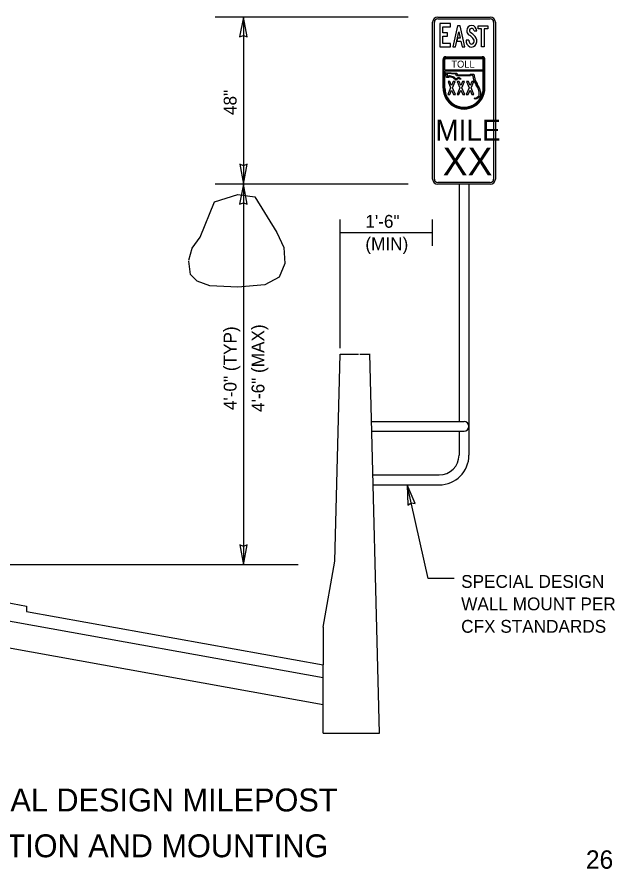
# Model space of a CAD drawing. Extents: x 57428 to 58066, y 11696 to 12105.
# Drawn here: x 57924.4 to 58054.8, y 11706.5 to 11892.4 of the extents above; entities that cross this region are included whole.
import ezdxf

# ---------------------------------------------------------------- set-up
doc = ezdxf.new("R2010")
doc.units = 0
for name, color, linetype in [('52', 7, 'Continuous'), ('62', 7, 'Continuous'), ('DimLines_dp', 7, 'Continuous'), ('NonPlottingEle_dp', 7, 'Continuous'), ('SheetLines_dp', 7, 'Continuous'), ('SignPanel', 7, 'Continuous'), ('TextMinor', 7, 'Continuous'), ('XSGrdLine_ex', 7, 'Continuous')]:
    doc.layers.add(name, color=color, linetype=linetype)

msp = doc.modelspace()

# ---------------------------------------------------------------- linework, layer by layer
at = {"layer": '52'}
msp.add_line((57985.74, 11772.84), (57842.57, 11772.84), dxfattribs=at)
at = {"layer": '62'}
msp.add_lwpolyline([(57961.87, 11839.32), (57962.57, 11841.92), (57964.37, 11844.33), (57967.47, 11852.08), (57972.57, 11853.68), (57976.27, 11853.18), (57981.07, 11845.33), (57982.58, 11842.12), (57982.78, 11838.62), (57981.57, 11835.62), (57978.47, 11833.91), (57972.57, 11833.41), (57966.47, 11833.71), (57963.67, 11834.71), (57962.27, 11836.22), (57961.87, 11839.12)], dxfattribs=at)
at = {"layer": 'DimLines_dp'}
for p, q in [((58009.68, 11892.38), (57967.6, 11892.38)), ((57973.78, 11892.38), (57972.94, 11888.03)), ((57973.78, 11892.38), (57973.78, 11855.89)), ((57974.59, 11888.03), (57973.78, 11892.38)), ((57972.94, 11888.03), (57973.78, 11888.36)), ((57973.78, 11888.36), (57974.59, 11888.03)), ((57973.78, 11861.88), (57973.78, 11772.84)), ((57973.78, 11859.91), (57972.97, 11860.24)), ((57972.97, 11860.24), (57973.78, 11855.89)), ((57973.78, 11859.91), (57972.97, 11860.24)), ((57972.97, 11860.24), (57973.78, 11855.89)), ((57973.78, 11855.89), (57974.62, 11860.24)), ((57974.62, 11860.24), (57973.78, 11859.91)), ((57973.78, 11855.89), (57974.62, 11860.24)), ((57974.62, 11860.24), (57973.78, 11859.91)), ((58009.68, 11855.89), (57967.6, 11855.89)), ((57973.78, 11855.89), (57972.94, 11851.54)), ((57974.59, 11851.54), (57973.78, 11855.89)), ((57972.94, 11851.54), (57973.78, 11851.87)), ((57973.78, 11851.87), (57974.59, 11851.54)), ((57994.89, 11820.11), (57994.89, 11848.22)), ((58015.03, 11842.47), (58015.03, 11848.22)), ((57994.89, 11845.38), (58015.03, 11845.38)), ((58009.47, 11790.29), (58009.6, 11785.87)), ((58011.21, 11786.23), (58009.47, 11790.29)), ((58014.05, 11769.85), (58009.47, 11790.29)), ((58009.6, 11785.87), (58010.35, 11786.37)), ((58010.35, 11786.37), (58011.21, 11786.23)), ((57973.78, 11776.86), (57972.97, 11777.19)), ((57972.97, 11777.19), (57973.78, 11772.84)), ((57973.78, 11772.84), (57974.62, 11777.19)), ((57974.62, 11777.19), (57973.78, 11776.86)), ((58019.7, 11769.85), (58014.05, 11769.85))]:
    msp.add_line(p, q, dxfattribs=at)
at = {"layer": 'NonPlottingEle_dp'}
for p, q in [((58020.8, 11855.89), (58020.8, 11804.14)), ((58022.96, 11855.89), (58022.96, 11796.77)), ((58001.72, 11804.14), (58021.88, 11804.14)), ((58001.78, 11801.98), (58021.88, 11801.98)), ((58020.8, 11801.98), (58020.8, 11796.77)), ((58002.02, 11792.45), (58016.48, 11792.45)), ((58002.08, 11790.29), (58016.48, 11790.29))]:
    msp.add_line(p, q, dxfattribs=at)
for centre, radius, end in [((58021.88, 11803.06), 1.08, 90), ((58016.48, 11796.77), 4.32, 0), ((58016.48, 11796.77), 6.48, 0)]:
    msp.add_arc(centre, radius, 270, end, dxfattribs=at)
at = {"layer": 'SignPanel'}
for p, q in [((58024.07, 11889.38), (58024.65, 11889.38)), ((58024.07, 11889.38), (58024.65, 11889.38)), ((58024.07, 11889.38), (58024.65, 11889.38)), ((58022.93, 11887.34), (58022.34, 11887.34)), ((58022.93, 11887.34), (58022.34, 11887.34)), ((58022.93, 11887.34), (58022.34, 11887.34)), ((58017.32, 11876.87), (58017.32, 11883.15)), ((58017.51, 11876.87), (58017.51, 11883.15)), ((58017.69, 11880.87), (58017.69, 11883.15)), ((58017.89, 11883.72), (58025.87, 11883.72)), ((58017.89, 11883.53), (58025.87, 11883.53)), ((58017.89, 11883.33), (58025.87, 11883.33)), ((58026.06, 11880.87), (58026.06, 11883.15)), ((58026.25, 11876.87), (58026.25, 11883.15)), ((58026.44, 11876.87), (58026.44, 11883.15)), ((58017.69, 11880.87), (58026.06, 11880.87)), ((58017.69, 11876.87), (58017.69, 11880.67)), ((58017.69, 11880.67), (58026.06, 11880.67)), ((58026.06, 11876.87), (58026.06, 11880.67)), ((58018.08, 11879.22), (58017.91, 11880.31)), ((58017.91, 11880.31), (58020.29, 11880.12)), ((58018.53, 11879.16), (58018.08, 11879.22)), ((58020.13, 11879.91), (58018.18, 11880.06)), ((58018.18, 11880.06), (58018.28, 11879.43)), ((58018.28, 11879.43), (58018.47, 11879.4)), ((58018.47, 11879.4), (58018.74, 11879.61)), ((58018.78, 11879.36), (58018.53, 11879.16)), ((58018.74, 11879.61), (58019.66, 11879.32)), ((58019.54, 11879.11), (58018.78, 11879.36)), ((58019.17, 11879.97), (58019.17, 11879.97)), ((58020.08, 11878.61), (58019.54, 11879.11)), ((58019.66, 11879.32), (58020.11, 11878.9)), ((58020.71, 11878.99), (58020.08, 11878.61)), ((58020.11, 11878.9), (58020.72, 11879.26)), ((58020.27, 11879.55), (58020.13, 11879.91)), ((58023.27, 11879.55), (58020.27, 11879.55)), ((58020.29, 11880.12), (58020.42, 11879.78)), ((58020.42, 11879.78), (58023.15, 11879.78)), ((58021.09, 11878.73), (58020.71, 11878.99)), ((58020.72, 11879.26), (58021.22, 11878.92)), ((58021.22, 11878.92), (58021.09, 11878.73)), ((58023.15, 11879.78), (58023.26, 11879.93)), ((58023.26, 11879.93), (58023.99, 11879.93)), ((58023.38, 11879.7), (58023.27, 11879.55)), ((58023.81, 11879.7), (58023.38, 11879.7)), ((58024.11, 11878.41), (58023.81, 11879.7)), ((58023.99, 11879.93), (58024.32, 11878.5)), ((58024.32, 11878.5), (58024.78, 11877.78)), ((58024.55, 11877.71), (58024.11, 11878.41)), ((58024.55, 11877.53), (58024.55, 11877.71)), ((58024.97, 11876.83), (58024.55, 11877.53)), ((58024.78, 11877.78), (58024.78, 11877.59)), ((58024.78, 11877.59), (58025.19, 11876.92)), ((58025.21, 11875.96), (58024.97, 11876.83)), ((58025.19, 11876.92), (58025.44, 11875.99)), ((58024.1, 11874.59), (58024.23, 11874.78)), ((58024.23, 11874.78), (58024.37, 11874.68)), ((58024.58, 11874.73), (58025.21, 11875.24)), ((58025.44, 11875.13), (58024.69, 11874.52)), ((58025.21, 11875.24), (58025.21, 11875.96)), ((58025.44, 11875.99), (58025.44, 11875.13)), ((58024.33, 11874.43), (58024.1, 11874.59)), ((58024.69, 11874.52), (58024.33, 11874.43)), ((58024.37, 11874.68), (58024.58, 11874.73))]:
    msp.add_line(p, q, dxfattribs=at)
for points in [[(58016.17, 11892.38), (58027.58, 11892.38)], [(58016.17, 11892), (58027.58, 11892)], [(58015.03, 11857.03), (58015.03, 11891.24)], [(58015.41, 11857.03), (58015.41, 11891.24)], [(58028.34, 11891.24), (58028.34, 11857.03)], [(58028.72, 11891.24), (58028.72, 11857.03)], [(58027.58, 11856.27), (58016.17, 11856.27)], [(58027.58, 11855.89), (58016.17, 11855.89)]]:
    msp.add_lwpolyline(points, dxfattribs=at)
for points in [[(58017.24, 11886.61), (58017.24, 11888.23), (58018.26, 11888.23), (58018.26, 11888.94), (58017.24, 11888.94), (58017.24, 11890.26), (58018.96, 11890.26), (58018.96, 11890.97), (58016.58, 11890.97), (58016.58, 11885.9), (58018.96, 11885.9), (58018.96, 11886.61)], [(58017.24, 11886.61), (58017.24, 11888.23), (58018.26, 11888.23), (58018.26, 11888.94), (58017.24, 11888.94), (58017.24, 11890.26), (58018.96, 11890.26), (58018.96, 11890.97), (58016.58, 11890.97), (58016.58, 11885.9), (58018.96, 11885.9), (58018.96, 11886.61)], [(58017.24, 11886.61), (58017.24, 11888.23), (58018.26, 11888.23), (58018.26, 11888.94), (58017.24, 11888.94), (58017.24, 11890.26), (58018.96, 11890.26), (58018.96, 11890.97), (58016.58, 11890.97), (58016.58, 11885.9), (58018.96, 11885.9), (58018.96, 11886.61)], [(58021.21, 11887.13), (58021.48, 11885.9), (58022.08, 11885.9), (58021.06, 11890.48), (58020.43, 11890.48), (58019.41, 11885.9), (58020.02, 11885.9), (58020.29, 11887.13)], [(58020.44, 11887.77), (58020.29, 11887.13), (58021.21, 11887.13), (58021.48, 11885.9), (58022.08, 11885.9), (58021.06, 11890.48), (58020.43, 11890.48), (58019.41, 11885.9), (58020.02, 11885.9), (58020.75, 11889.17), (58021.06, 11887.77)], [(58020.44, 11887.77), (58020.29, 11887.13), (58021.21, 11887.13), (58021.48, 11885.9), (58022.08, 11885.9), (58021.06, 11890.48), (58020.43, 11890.48), (58019.41, 11885.9), (58020.02, 11885.9), (58020.75, 11889.17), (58021.06, 11887.77)], [(58025.72, 11889.84), (58024.94, 11889.84), (58024.94, 11890.48), (58027.08, 11890.48), (58027.08, 11889.84), (58026.3, 11889.84), (58026.3, 11885.9), (58025.72, 11885.9)], [(58025.72, 11889.84), (58024.94, 11889.84), (58024.94, 11890.48), (58027.08, 11890.48), (58027.08, 11889.84), (58026.3, 11889.84), (58026.3, 11885.9), (58025.72, 11885.9)], [(58025.72, 11889.84), (58024.94, 11889.84), (58024.94, 11890.48), (58027.08, 11890.48), (58027.08, 11889.84), (58026.3, 11889.84), (58026.3, 11885.9), (58025.72, 11885.9)], [(58020.75, 11889.17), (58021.06, 11887.77), (58020.44, 11887.77)], [(58018.77, 11875.45), (58019.17, 11876.43), (58019.58, 11875.45), (58020.01, 11875.45), (58019.39, 11876.94), (58019.96, 11878.3), (58019.53, 11878.3), (58019.17, 11877.45), (58018.82, 11878.3), (58018.39, 11878.3), (58018.96, 11876.94), (58018.34, 11875.45)], [(58020.78, 11875.45), (58021.19, 11876.43), (58021.6, 11875.45), (58022.03, 11875.45), (58021.4, 11876.94), (58021.98, 11878.3), (58021.55, 11878.3), (58021.19, 11877.45), (58020.83, 11878.3), (58020.41, 11878.3), (58020.98, 11876.94), (58020.36, 11875.45)], [(58022.8, 11875.45), (58023.21, 11876.43), (58023.61, 11875.45), (58024.04, 11875.45), (58023.42, 11876.94), (58023.99, 11878.3), (58023.56, 11878.3), (58023.21, 11877.45), (58022.85, 11878.3), (58022.42, 11878.3), (58022.99, 11876.94), (58022.37, 11875.45)]]:
    msp.add_lwpolyline(points, close=True, dxfattribs=at)
for centre, radius, start, end in [((58016.17, 11891.24), 1.14, 90, 180), ((58016.17, 11891.24), 0.76, 90, 180), ((58027.58, 11891.24), 1.14, 0, 90), ((58027.58, 11891.24), 0.76, 0, 90), ((58016.17, 11857.03), 1.14, 180, 270), ((58016.17, 11857.03), 0.76, 180, 270), ((58027.58, 11857.03), 1.14, 270, 360), ((58027.58, 11857.03), 0.76, 270, 360)]:
    msp.add_arc(centre, radius, start, end, dxfattribs=at)
for centre, major_axis, ratio, start_param, end_param in [((58023.56, 11889.35), (0, 1.19), 0.91923, 4.736267, 7.790596), ((58023.56, 11889.35), (0, 1.19), 0.91923, 4.736267, 7.790596), ((58023.56, 11889.35), (0, 1.19), 0.91923, 4.736267, 7.790596), ((58023.49, 11889.41), (0, 0.46), 0.91923, 0.87378, 2.656959), ((58023.49, 11889.41), (0, 0.46), 0.91923, 0.87378, 2.656959), ((58023.49, 11889.41), (0, 0.46), 0.91923, 0.87378, 2.656959), ((58023.56, 11889.34), (0, 0.558), 0.91923, 4.786904, 7.140738), ((58023.56, 11889.34), (0, 0.558), 0.91923, 4.786904, 7.140738), ((58023.56, 11889.34), (0, 0.558), 0.91923, 4.786904, 7.140738), ((58023.45, 11889.39), (0, 1.07), 0.91923, 1.534831, 2.511766), ((58023.45, 11889.39), (0, 1.07), 0.91923, 1.534831, 2.511766), ((58023.45, 11889.39), (0, 1.07), 0.91923, 1.534831, 2.511766), ((58020.85, 11884.45), (0, 4.63), 0.91923, 5.515137, 5.786988), ((58020.85, 11884.45), (0, 4.63), 0.91923, 5.515137, 5.786988), ((58020.85, 11884.45), (0, 4.63), 0.91923, 5.515137, 5.786988), ((58021.36, 11885.15), (0, 4.39), 0.91923, 5.462886, 5.782242), ((58021.36, 11885.15), (0, 4.39), 0.91923, 5.462886, 5.782242), ((58021.36, 11885.15), (0, 4.39), 0.91923, 5.462886, 5.782242), ((58023.37, 11887.15), (0, 0.792), 0.91923, 4.254409, 5.632398), ((58023.37, 11887.15), (0, 0.792), 0.91923, 4.254409, 5.632398), ((58023.37, 11887.15), (0, 0.792), 0.91923, 4.254409, 5.632398), ((58023.38, 11887.15), (0, 1.42), 0.91923, 4.260987, 5.485755), ((58023.38, 11887.15), (0, 1.42), 0.91923, 4.260987, 5.485755), ((58023.38, 11887.15), (0, 1.42), 0.91923, 4.260987, 5.485755), ((58023.71, 11887.27), (0, 1.5), 0.91923, 1.526364, 2.701682), ((58023.71, 11887.27), (0, 1.5), 0.91923, 1.526364, 2.701682), ((58023.71, 11887.27), (0, 1.5), 0.91923, 1.526364, 2.701682), ((58023.77, 11887.3), (0, 0.911), 0.91923, 1.524757, 2.28214), ((58023.77, 11887.3), (0, 0.911), 0.91923, 1.524757, 2.28214), ((58023.77, 11887.3), (0, 0.911), 0.91923, 1.524757, 2.28214), ((58023.53, 11887.08), (0, 1.24), 0.91923, 2.786047, 4.251692), ((58023.53, 11887.08), (0, 1.24), 0.91923, 2.786047, 4.251692), ((58023.53, 11887.08), (0, 1.24), 0.91923, 2.786047, 4.251692), ((58023.55, 11887.07), (0, 0.581), 0.91923, 2.261787, 4.23006), ((58023.55, 11887.07), (0, 0.581), 0.91923, 2.261787, 4.23006), ((58023.55, 11887.07), (0, 0.581), 0.91923, 2.261787, 4.23006), ((58017.89, 11883.14), (0, 0.57), 0.9997, 0, 1.570796), ((58017.89, 11883.14), (0, 0.38), 0.9997, 0, 1.570796), ((58017.89, 11883.14), (0, 0.19), 0.9997, 0, 1.570796), ((58025.87, 11883.14), (0, 0.57), 0.9997, 4.712389, 6.283185), ((58025.87, 11883.14), (0, 0.38), 0.9997, 4.712389, 6.283185), ((58025.87, 11883.14), (0, 0.19), 0.9997, 4.712389, 6.283185), ((58021.88, 11876.87), (0, -4.56), 0.9997, 4.712389, 7.853982), ((58021.88, 11876.87), (0, -4.37), 0.9997, 4.712389, 7.853982), ((58021.88, 11876.87), (0, -4.18), 0.9997, 4.712389, 7.853982)]:
    msp.add_ellipse(centre, major_axis=major_axis, ratio=ratio, start_param=start_param, end_param=end_param, dxfattribs=at)
at = {"layer": 'XSGrdLine_ex'}
for p, q in [((57993.74, 11773.63), (57994.89, 11818.81)), ((57994.89, 11818.81), (57998.87, 11818.81)), ((57999.15, 11818.81), (58001.35, 11818.81)), ((58003.46, 11736.1), (58001.35, 11818.87)), ((57991.17, 11759.25), (57993.74, 11773.63)), ((57920.31, 11764.96), (57926.48, 11763.85)), ((57926.48, 11763.85), (57926.48, 11762.68)), ((57926.48, 11762.68), (57991.17, 11751.04)), ((57991.17, 11748.2), (57919.9, 11761.02)), ((57991.17, 11759.25), (57991.17, 11751.04)), ((57922.37, 11754.76), (57991.17, 11742.38)), ((57991.17, 11736.1), (57991.17, 11751.04)), ((57991.17, 11736.1), (58003.46, 11736.1))]:
    msp.add_line(p, q, dxfattribs=at)

# ---------------------------------------------------------------- texts
at = {"layer": 'DimLines_dp'}
for s, p in [('48"', (57972.28, 11871)), ('4\'-0" (TYP)', (57972.28, 11806.61)), ('4\'-6" (MAX)', (57978.36, 11806.21))]:
    msp.add_text(s, height=2.8, rotation=90, dxfattribs=at).set_placement(p)
for s, p in [('1\'-6"', (58000.37, 11846.4)), ('(MIN)', (58000.37, 11841.5)), ('SPECIAL DESIGN', (58021.26, 11767.81)), ('WALL MOUNT PER', (58021.26, 11762.91)), ('CFX STANDARDS', (58021.26, 11758.01))]:
    msp.add_text(s, height=2.8, dxfattribs=at).set_placement(p)
at = {"layer": 'SheetLines_dp'}
for s, p in [('SPECIAL DESIGN MILEPOST ', (57902.9, 11719.02)), (' LOCATION AND MOUNTING  ', (57902.04, 11709.02))]:
    msp.add_text(s, height=5, rotation=360, dxfattribs=at).set_placement(p)
at = {"layer": 'SignPanel'}
for s, height, p in [('TOLL', 1.519, (58019.12, 11881.34)), ('MILE', 4.562, (58015.62, 11865.39)), ('XX', 6.083, (58017.23, 11857.82))]:
    msp.add_text(s, height=height, dxfattribs=at).set_placement(p)
at = {"layer": 'TextMinor'}
msp.add_text('26', height=4, rotation=360, dxfattribs=at).set_placement((58048.46, 11706.52))

doc.saveas('drawing.dxf')
